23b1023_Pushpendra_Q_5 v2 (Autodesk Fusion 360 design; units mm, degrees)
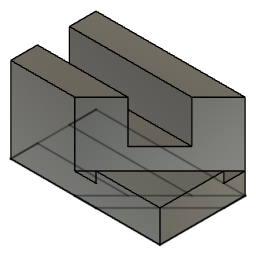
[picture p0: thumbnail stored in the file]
sketch "Sketch1" plane through (0, 0, 0) normal (0, 0, 1) x axis (1, 0, 0)
  line L1 (-5, 50) -> (-75, 50)
  line L2 (-75, 10) -> (-75, 50)
  line L3 (-45, 10) -> (-75, 10)
  line L4 (-5, 50) -> (-45, 10)
  line L5 (-35, 10) -> (-45, 10)
  line L6 (-5, 10) -> (-35, 10)
  line L7 (-5, 10) -> (-5, 50)
  line L8 (-35, 10) -> (-45, 10)
  line L9 (-5, 40) -> (-5, 50)
  line L10 (-5, 40) -> (-35, 10)
  line L11 (-75, 37.5) -> (-75, 50)
  line L12 (-75, 22.5) -> (-75, 10)
  line L13 (-32.5, 22.5) -> (-75, 22.5)
  line L14 (-17.5, 37.5) -> (-75, 37.5)
  point P8 (-5, 40)
  point P9 (-75, 37.5)
  point P11 (-32.5, 22.5)
  point P12 (-17.5, 37.5)
  point P2 (-75, 50)
  point P4 (-75, 10)
  point P3 (-5, 50)
  point P5 (-45, 10)
  point P7 (-5, 10)
  point P10 (-75, 22.5)
  point P1 (0, 0)
  horizontal L1
  perpendicular L1 L2
  perpendicular L2 L3
  parallel L3 L5
  parallel L5 L6
  perpendicular L6 L7
  coincident L7 P8
  coincident L2 P9
  perpendicular L3 L12
  coincident L4 P11
  perpendicular L12 L13
  coincident L4 P12
  perpendicular L2 L14
  parallel L4 L10
  dimension "d1" distance P2 P4 = 40
  dimension "d2" distance P3 P5 = 56.5685
  dimension "d3" distance P3 P7 = 40
  dimension "d4" distance P2 P9 = 12.5
  dimension "d5" distance P4 P10 = 12.5
  dimension "d6" distance P1 L1 = 50
  dimension "d7" distance P1 L10 = 31.8198
  dimension "d8" distance P1 L4 = 38.8909
extrude "Extrude2" new body sketch "Sketch1" profile of L2 L4 L13 L14 along normal blind 20
extrude "Extrude3" add sketch "Sketch1" profile of L1 L2 L3 L4 L11 L12 L13 L14 along normal blind 40
extrude "Extrude4" add sketch "Sketch1" profile of L4 L5 L7 L8 L9 L10 along normal blind 10
extrude "Extrude5" add sketch "Sketch1" profile of L6 L7 L10 along normal blind 15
